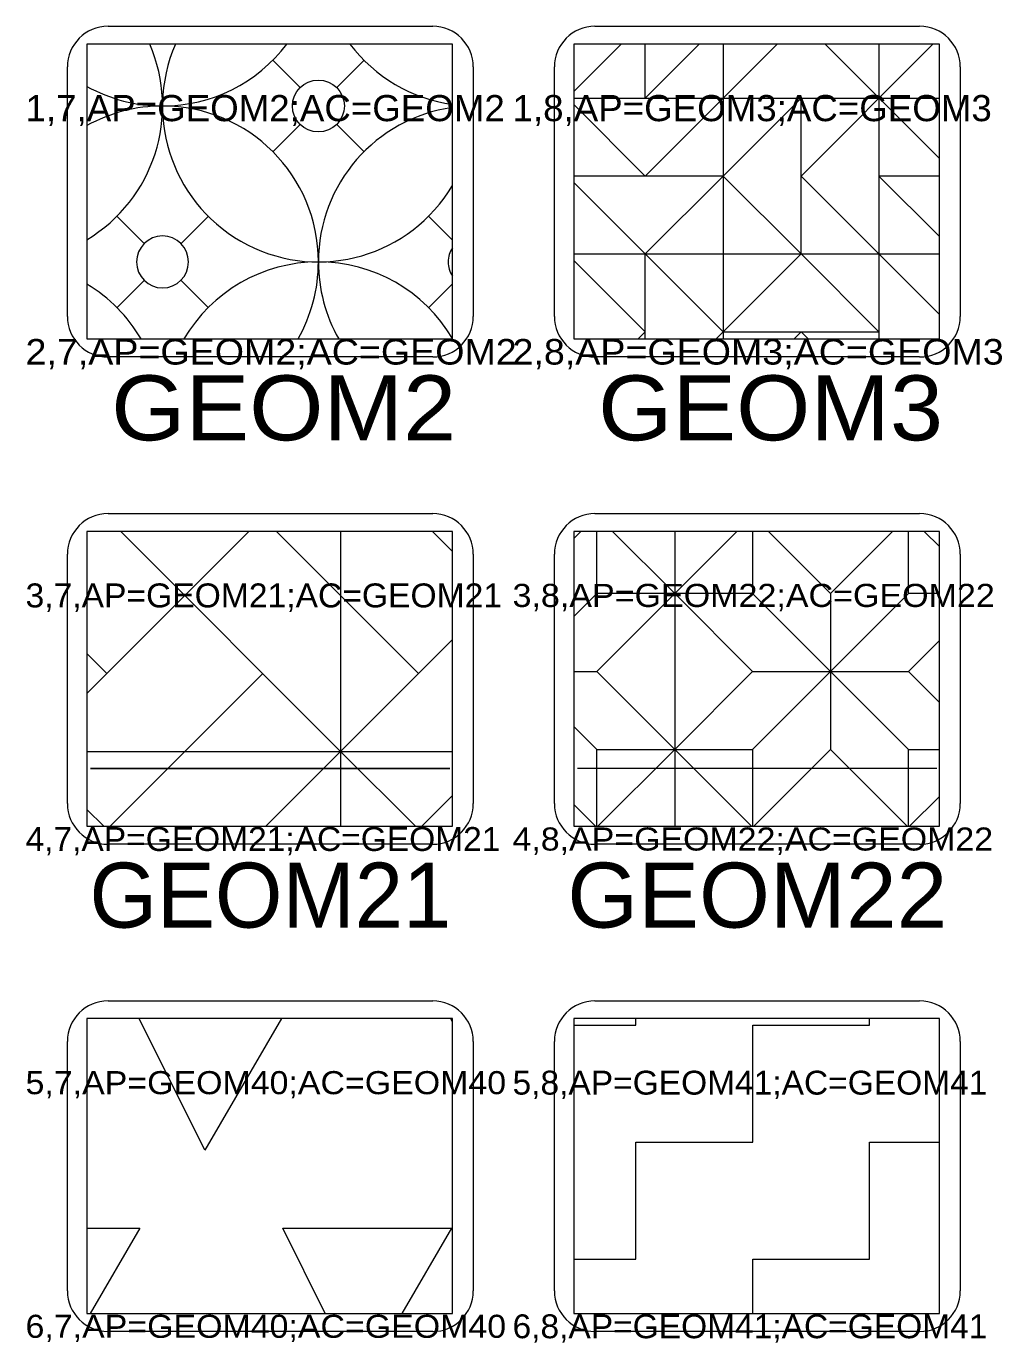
# Model space of a CAD drawing. Extents: x 95935 to 95946.4, y 95971.2 to 95974.7.
# Drawn here: x 95938.635 to 95939.831, y 95973.111 to 95974.732 of the extents above; entities that cross this region are included whole.
import ezdxf
from ezdxf.enums import TextEntityAlignment as Align

# ---------------------------------------------------------------- set-up
doc = ezdxf.new("R2010")
doc.units = 0
doc.header["$LTSCALE"] = 0.032
for name, color, linetype, lineweight in [('1', 7, 'Continuous', 13), ('2', 7, 'Continuous', 13), ('25', 7, 'Continuous', 13), ('6', 7, 'Continuous', 13), ('63', 7, 'Continuous', 13)]:
    doc.layers.add(name, color=color, linetype=linetype, lineweight=lineweight)
doc.layers.add('20', color=7, linetype='Continuous')

msp = doc.modelspace()

# ---------------------------------------------------------------- linework, layer by layer
at = {"layer": '1'}
for p, q in [((95938.7357, 95974.7318), (95939.1357, 95974.7318)), ((95939.3357, 95974.7318), (95939.7357, 95974.7318)), ((95938.6857, 95974.3747), (95938.6857, 95974.6818)), ((95939.1857, 95974.6818), (95939.1857, 95974.3747)), ((95939.2857, 95974.3747), (95939.2857, 95974.6818)), ((95939.7857, 95974.6818), (95939.7857, 95974.3747)), ((95939.1357, 95974.3247), (95938.7357, 95974.3247)), ((95939.7357, 95974.3247), (95939.3357, 95974.3247)), ((95938.7357, 95974.1318), (95939.1357, 95974.1318)), ((95939.3357, 95974.1318), (95939.7357, 95974.1318)), ((95938.6857, 95973.7747), (95938.6857, 95974.0818)), ((95939.1857, 95974.0818), (95939.1857, 95973.7747)), ((95939.2857, 95973.7747), (95939.2857, 95974.0818)), ((95939.7857, 95974.0818), (95939.7857, 95973.7747)), ((95939.1357, 95973.7247), (95938.7357, 95973.7247)), ((95939.7357, 95973.7247), (95939.3357, 95973.7247)), ((95938.7357, 95973.5318), (95939.1357, 95973.5318)), ((95939.3357, 95973.5318), (95939.7357, 95973.5318)), ((95938.6857, 95973.1747), (95938.6857, 95973.4818)), ((95939.1857, 95973.4818), (95939.1857, 95973.1747)), ((95939.2857, 95973.1747), (95939.2857, 95973.4818)), ((95939.7857, 95973.4818), (95939.7857, 95973.1747)), ((95939.1357, 95973.1247), (95938.7357, 95973.1247)), ((95939.7357, 95973.1247), (95939.3357, 95973.1247))]:
    msp.add_line(p, q, dxfattribs=at)
for centre, start, end in [((95938.7357, 95974.6818), 90, 180), ((95939.1357, 95974.6818), 0, 90), ((95939.3357, 95974.6818), 90, 180), ((95939.7357, 95974.6818), 0, 90), ((95938.7357, 95974.3747), 180, 270), ((95939.1357, 95974.3747), 270, 0), ((95939.3357, 95974.3747), 180, 270), ((95939.7357, 95974.3747), 270, 0), ((95938.7357, 95974.0818), 90, 180), ((95939.1357, 95974.0818), 0, 90), ((95939.3357, 95974.0818), 90, 180), ((95939.7357, 95974.0818), 0, 90), ((95938.7357, 95973.7747), 180, 270), ((95939.1357, 95973.7747), 270, 0), ((95939.3357, 95973.7747), 180, 270), ((95939.7357, 95973.7747), 270, 0), ((95938.7357, 95973.4818), 90, 180), ((95939.1357, 95973.4818), 0, 90), ((95939.3357, 95973.4818), 90, 180), ((95939.7357, 95973.4818), 0, 90), ((95938.7357, 95973.1747), 180, 270), ((95939.1357, 95973.1747), 270, 0), ((95939.3357, 95973.1747), 180, 270), ((95939.7357, 95973.1747), 270, 0)]:
    msp.add_arc(centre, 0.05, start, end, dxfattribs=at)
at = {"layer": '2'}
for points in [[(95939.1601, 95974.7099), (95938.7097, 95974.7099), (95938.7097, 95974.3468), (95939.1601, 95974.3468)], [(95939.7601, 95974.7099), (95939.3097, 95974.7099), (95939.3097, 95974.3468), (95939.7601, 95974.3468)], [(95939.1601, 95974.1099), (95938.7097, 95974.1099), (95938.7097, 95973.7468), (95939.1601, 95973.7468)], [(95939.7601, 95974.1099), (95939.3097, 95974.1099), (95939.3097, 95973.7468), (95939.7601, 95973.7468)], [(95939.1601, 95973.5099), (95938.7097, 95973.5099), (95938.7097, 95973.1468), (95939.1601, 95973.1468)], [(95939.7601, 95973.5099), (95939.3097, 95973.5099), (95939.3097, 95973.1468), (95939.7601, 95973.1468)]]:
    msp.add_lwpolyline(points, close=True, dxfattribs=at)
at = {"layer": '25'}
for p, q in [((95939.1569, 95973.8178), (95938.7141, 95973.8178)), ((95938.7141, 95973.8178), (95939.1569, 95973.8178)), ((95939.7569, 95973.8178), (95939.3141, 95973.8178))]:
    msp.add_line(p, q, dxfattribs=at)
at = {"layer": '6'}
for p, q in [((95939.3097, 95974.6516), (95939.368, 95974.7099)), ((95939.4936, 95974.7099), (95939.4936, 95974.3468)), ((95939.4936, 95974.6435), (95939.56, 95974.7099)), ((95939.5896, 95974.5475), (95939.752, 95974.7099)), ((95939.6192, 95974.7099), (95939.7601, 95974.569)), ((95939.6856, 95974.7099), (95939.6856, 95974.3468)), ((95938.9723, 95974.6563), (95938.9386, 95974.69)), ((95939.0175, 95974.6563), (95939.0512, 95974.69)), ((95939.3097, 95974.6435), (95939.7601, 95974.6435)), ((95939.3976, 95974.5475), (95939.4936, 95974.6435)), ((95939.3097, 95974.6354), (95939.3976, 95974.5475)), ((95938.9723, 95974.6111), (95938.9386, 95974.5774)), ((95939.0175, 95974.6111), (95939.0512, 95974.5774)), ((95939.4936, 95974.5475), (95939.3097, 95974.5475)), ((95939.3976, 95974.4515), (95939.4936, 95974.5475)), ((95939.6856, 95974.4515), (95939.5896, 95974.5475)), ((95939.3097, 95974.5394), (95939.3976, 95974.4515)), ((95938.7469, 95974.4977), (95938.7801, 95974.4645)), ((95938.8589, 95974.4977), (95938.8257, 95974.4645)), ((95939.1309, 95974.4977), (95939.1601, 95974.4685)), ((95939.3097, 95974.4515), (95939.7601, 95974.4515)), ((95939.3976, 95974.4515), (95939.4936, 95974.3555)), ((95939.3976, 95974.3468), (95939.3976, 95974.4515)), ((95939.7601, 95974.377), (95939.6856, 95974.4515)), ((95938.7469, 95974.3857), (95938.7801, 95974.4189)), ((95938.8589, 95974.3857), (95938.8257, 95974.4189)), ((95939.1309, 95974.3857), (95939.1601, 95974.4149)), ((95939.4936, 95974.3555), (95939.4849, 95974.3468)), ((95938.9093, 95974.1099), (95938.7097, 95973.9103)), ((95938.7513, 95974.1099), (95939.0223, 95973.8389)), ((95939.0223, 95974.0309), (95938.9433, 95974.1099)), ((95939.0223, 95974.1099), (95939.0223, 95973.7468)), ((95939.1353, 95974.1099), (95939.1601, 95974.0851)), ((95939.3184, 95974.1099), (95939.3097, 95974.1012)), ((95939.3379, 95974.0334), (95939.3379, 95974.1099)), ((95939.4339, 95974.0334), (95939.3574, 95974.1099)), ((95939.4339, 95974.1099), (95939.4339, 95973.7468)), ((95939.5104, 95974.1099), (95939.4339, 95974.0334)), ((95939.5299, 95974.1099), (95939.5299, 95974.0334)), ((95939.7601, 95974.0912), (95939.7414, 95974.1099)), ((95939.0223, 95974.0309), (95939.1183, 95973.9349)), ((95939.3097, 95974.0052), (95939.3379, 95974.0334)), ((95939.4339, 95974.0334), (95939.3379, 95974.0334)), ((95939.5299, 95974.0334), (95939.4339, 95974.0334)), ((95939.5299, 95973.8414), (95939.7219, 95974.0334)), ((95939.5299, 95974.0334), (95939.7219, 95973.8414)), ((95939.6259, 95974.0334), (95939.6259, 95973.8414)), ((95939.1601, 95973.9767), (95939.0223, 95973.8389)), ((95938.7097, 95973.9595), (95938.7343, 95973.9349)), ((95938.8303, 95973.8389), (95938.9263, 95973.9349)), ((95939.3097, 95973.9374), (95939.3379, 95973.9374)), ((95939.5299, 95973.9374), (95939.7219, 95973.9374)), ((95939.3097, 95973.8696), (95939.3379, 95973.8414)), ((95938.7097, 95973.8389), (95939.1601, 95973.8389)), ((95938.8303, 95973.8389), (95938.7382, 95973.7468)), ((95939.0223, 95973.8389), (95938.9302, 95973.7468)), ((95939.0223, 95973.8389), (95939.1144, 95973.7468)), ((95939.3379, 95973.8414), (95939.4339, 95973.8414)), ((95939.3379, 95973.7468), (95939.3379, 95973.8414)), ((95939.3393, 95973.7468), (95939.4339, 95973.8414)), ((95939.4339, 95973.8414), (95939.5299, 95973.8414)), ((95939.4339, 95973.8414), (95939.5285, 95973.7468)), ((95939.5299, 95973.8414), (95939.5299, 95973.7468)), ((95939.1601, 95973.7847), (95939.1222, 95973.7468)), ((95939.7233, 95973.7468), (95939.7601, 95973.7836)), ((95938.7097, 95973.7675), (95938.7304, 95973.7468)), ((95939.3097, 95973.7736), (95939.3365, 95973.7468)), ((95938.8549, 95973.3478), (95938.7739, 95973.5099)), ((95938.9495, 95973.5099), (95938.8549, 95973.3478)), ((95939.1601, 95973.5055), (95939.1579, 95973.5099)), ((95939.674, 95973.3578), (95939.7601, 95973.3578)), ((95939.0034, 95973.1468), (95938.9509, 95973.2518)), ((95939.53, 95973.1468), (95939.53, 95973.2138))]:
    msp.add_line(p, q, dxfattribs=at)
for points in [[(95939.464, 95974.7099), (95939.3976, 95974.6435), (95939.3976, 95974.7099)], [(95939.7601, 95974.5475), (95939.6856, 95974.5475), (95939.7601, 95974.473)], [(95939.3889, 95974.3468), (95939.3976, 95974.3555), (95939.3097, 95974.4434)], [(95939.5809, 95974.3468), (95939.5896, 95974.3555), (95939.5983, 95974.3468)], [(95939.7024, 95974.1099), (95939.6259, 95974.0334), (95939.5494, 95974.1099)], [(95939.7601, 95974.0334), (95939.7219, 95974.0334), (95939.7219, 95974.1099)], [(95939.4339, 95973.8414), (95939.3379, 95973.9374), (95939.4339, 95974.0334)], [(95939.4339, 95974.0334), (95939.5299, 95973.9374), (95939.4339, 95973.8414)], [(95939.7601, 95973.8992), (95939.7219, 95973.9374), (95939.7601, 95973.9756)], [(95939.5313, 95973.7468), (95939.6259, 95973.8414), (95939.7205, 95973.7468)], [(95939.7219, 95973.7468), (95939.7219, 95973.8414), (95939.7601, 95973.8414)], [(95939.3097, 95973.5018), (95939.386, 95973.5018), (95939.386, 95973.5099)], [(95939.53, 95973.5018), (95939.674, 95973.5018), (95939.674, 95973.5099)], [(95939.386, 95973.3578), (95939.53, 95973.3578), (95939.53, 95973.5018)], [(95939.3097, 95973.2138), (95939.386, 95973.2138), (95939.386, 95973.3578)], [(95939.53, 95973.2138), (95939.674, 95973.2138), (95939.674, 95973.3578)], [(95938.7097, 95973.2518), (95938.7749, 95973.2518), (95938.7137, 95973.1468)], [(95938.9509, 95973.2518), (95939.1589, 95973.2518), (95939.0977, 95973.1468)]]:
    msp.add_lwpolyline(points, dxfattribs=at)
for points in [[(95939.5896, 95974.4515), (95939.5896, 95974.6435), (95939.4936, 95974.5475)], [(95939.4936, 95974.3555), (95939.6856, 95974.3555), (95939.5896, 95974.4515)]]:
    msp.add_lwpolyline(points, close=True, dxfattribs=at)
msp.add_circle((95938.9949, 95974.6337), 0.032, dxfattribs=at)
for centre, radius, start, end in [((95938.6109, 95974.6337), 0.192, 300.971, 23.383), ((95938.8029, 95974.8257), 0.192, 270, 322.906), ((95938.9949, 95974.6337), 0.192, 156.617, 329.3634), ((95939.1869, 95974.8257), 0.192, 217.094, 261.9763), ((95938.8029, 95974.8257), 0.192, 240.9616, 270), ((95938.8029, 95974.4417), 0.192, 90, 119.0384), ((95938.8029, 95974.4417), 0.192, 0, 90), ((95939.1869, 95974.4417), 0.192, 98.0237, 180), ((95938.8029, 95974.4417), 0.032, 90, 180), ((95938.8029, 95974.4417), 0.032, 0, 90), ((95939.1869, 95974.4417), 0.032, 146.8771, 180), ((95938.8029, 95974.4417), 0.032, 180, 270), ((95938.8029, 95974.4417), 0.032, 270, 360), ((95938.9949, 95974.2497), 0.192, 30.6366, 149.6202), ((95938.8029, 95974.4417), 0.192, 330.3783, 360), ((95939.1869, 95974.4417), 0.192, 180, 209.6217), ((95939.1869, 95974.4417), 0.032, 180, 213.1229), ((95938.6109, 95974.2497), 0.192, 30.3798, 59.029)]:
    msp.add_arc(centre, radius, start, end, dxfattribs=at)

# ---------------------------------------------------------------- texts
at = {"layer": '20'}
for s, width, p in [(' GEOM2', 1.1, (95938.9358, 95974.222)), (' GEOM3', 1.1, (95939.5357, 95974.222)), ('GEOM22', 1.05, (95939.5357, 95973.622))]:
    msp.add_text(s, height=0.08, dxfattribs=dict(at, width=width)).set_placement(p, align=Align.CENTER)
msp.add_text('GEOM21', height=0.08, dxfattribs=at).set_placement((95938.9358, 95973.622), align=Align.CENTER)
at = {"layer": '63'}
for s, height, width, p in [('1,7,AP=GEOM2;AC=GEOM2', 0.0322, 1.05, (95938.6341, 95974.615)), ('1,8,AP=GEOM3;AC=GEOM3', 0.0322, 1.05, (95939.2341, 95974.615)), ('2,7,AP=GEOM2;AC=GEOM2', 0.0315, 1.1, (95938.6341, 95974.3153)), ('2,8,AP=GEOM3;AC=GEOM3', 0.0315, 1.1, (95939.2341, 95974.3153)), ('3,7,AP=GEOM21;AC=GEOM21', 0.0295, 1.05, (95938.6341, 95974.0163)), ('3,8,AP=GEOM22;AC=GEOM22', 0.0285, 1.1, (95939.2341, 95974.0168)), ('4,7,AP=GEOM21;AC=GEOM21', 0.0294, 1.05, (95938.6341, 95973.7164)), ('4,8,AP=GEOM22;AC=GEOM22', 0.0284, 1.1, (95939.2341, 95973.7169)), ('5,7,AP=GEOM40;AC=GEOM40', 0.0284, 1.1, (95938.6341, 95973.4169)), ('5,8,AP=GEOM41;AC=GEOM41', 0.0294, 1.05, (95939.2341, 95973.4164)), ('6,7,AP=GEOM40;AC=GEOM40', 0.0284, 1.1, (95938.6341, 95973.1169)), ('6,8,AP=GEOM41;AC=GEOM41', 0.0294, 1.05, (95939.2341, 95973.1164))]:
    msp.add_text(s, height=height, dxfattribs=dict(at, width=width)).set_placement(p)

doc.saveas('drawing.dxf')
